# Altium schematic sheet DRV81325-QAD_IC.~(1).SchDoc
size 431 x 279 mm; Date: Not shown in title block; ApprovedBy: Not shown in title block; CheckedBy: Not shown in title block; Author: Not shown in title block; CompanyName: Not shown in title block; Engineer: Not shown in title block; Organization: Not shown in title block; Address1: Not shown in title block; Address2: Not shown in title block; Address3: Not shown in title block; Address4: Not shown in title block; DocumentNumber: 1; Revision: Use project parameter SCH_Rev; SheetNumber: 3; SheetTotal: 5; PageSetup: Record=PageOptions¦CenterHorizontal=True¦CenterVertical=True¦PrintScale=1.00¦XCorrection=1.00¦YCorrection=1.00¦PrintKind=0¦BorderSize=5000000¦LeftOffset=0¦BottomOffset=0¦Orientation=2¦PaperLength=1000¦PaperWidth=1000¦Scale=100¦PaperSource=15¦PrintQuality=600¦MediaType=1¦DitherType=10¦PaperKind=Letter¦PrintScaleMode=1
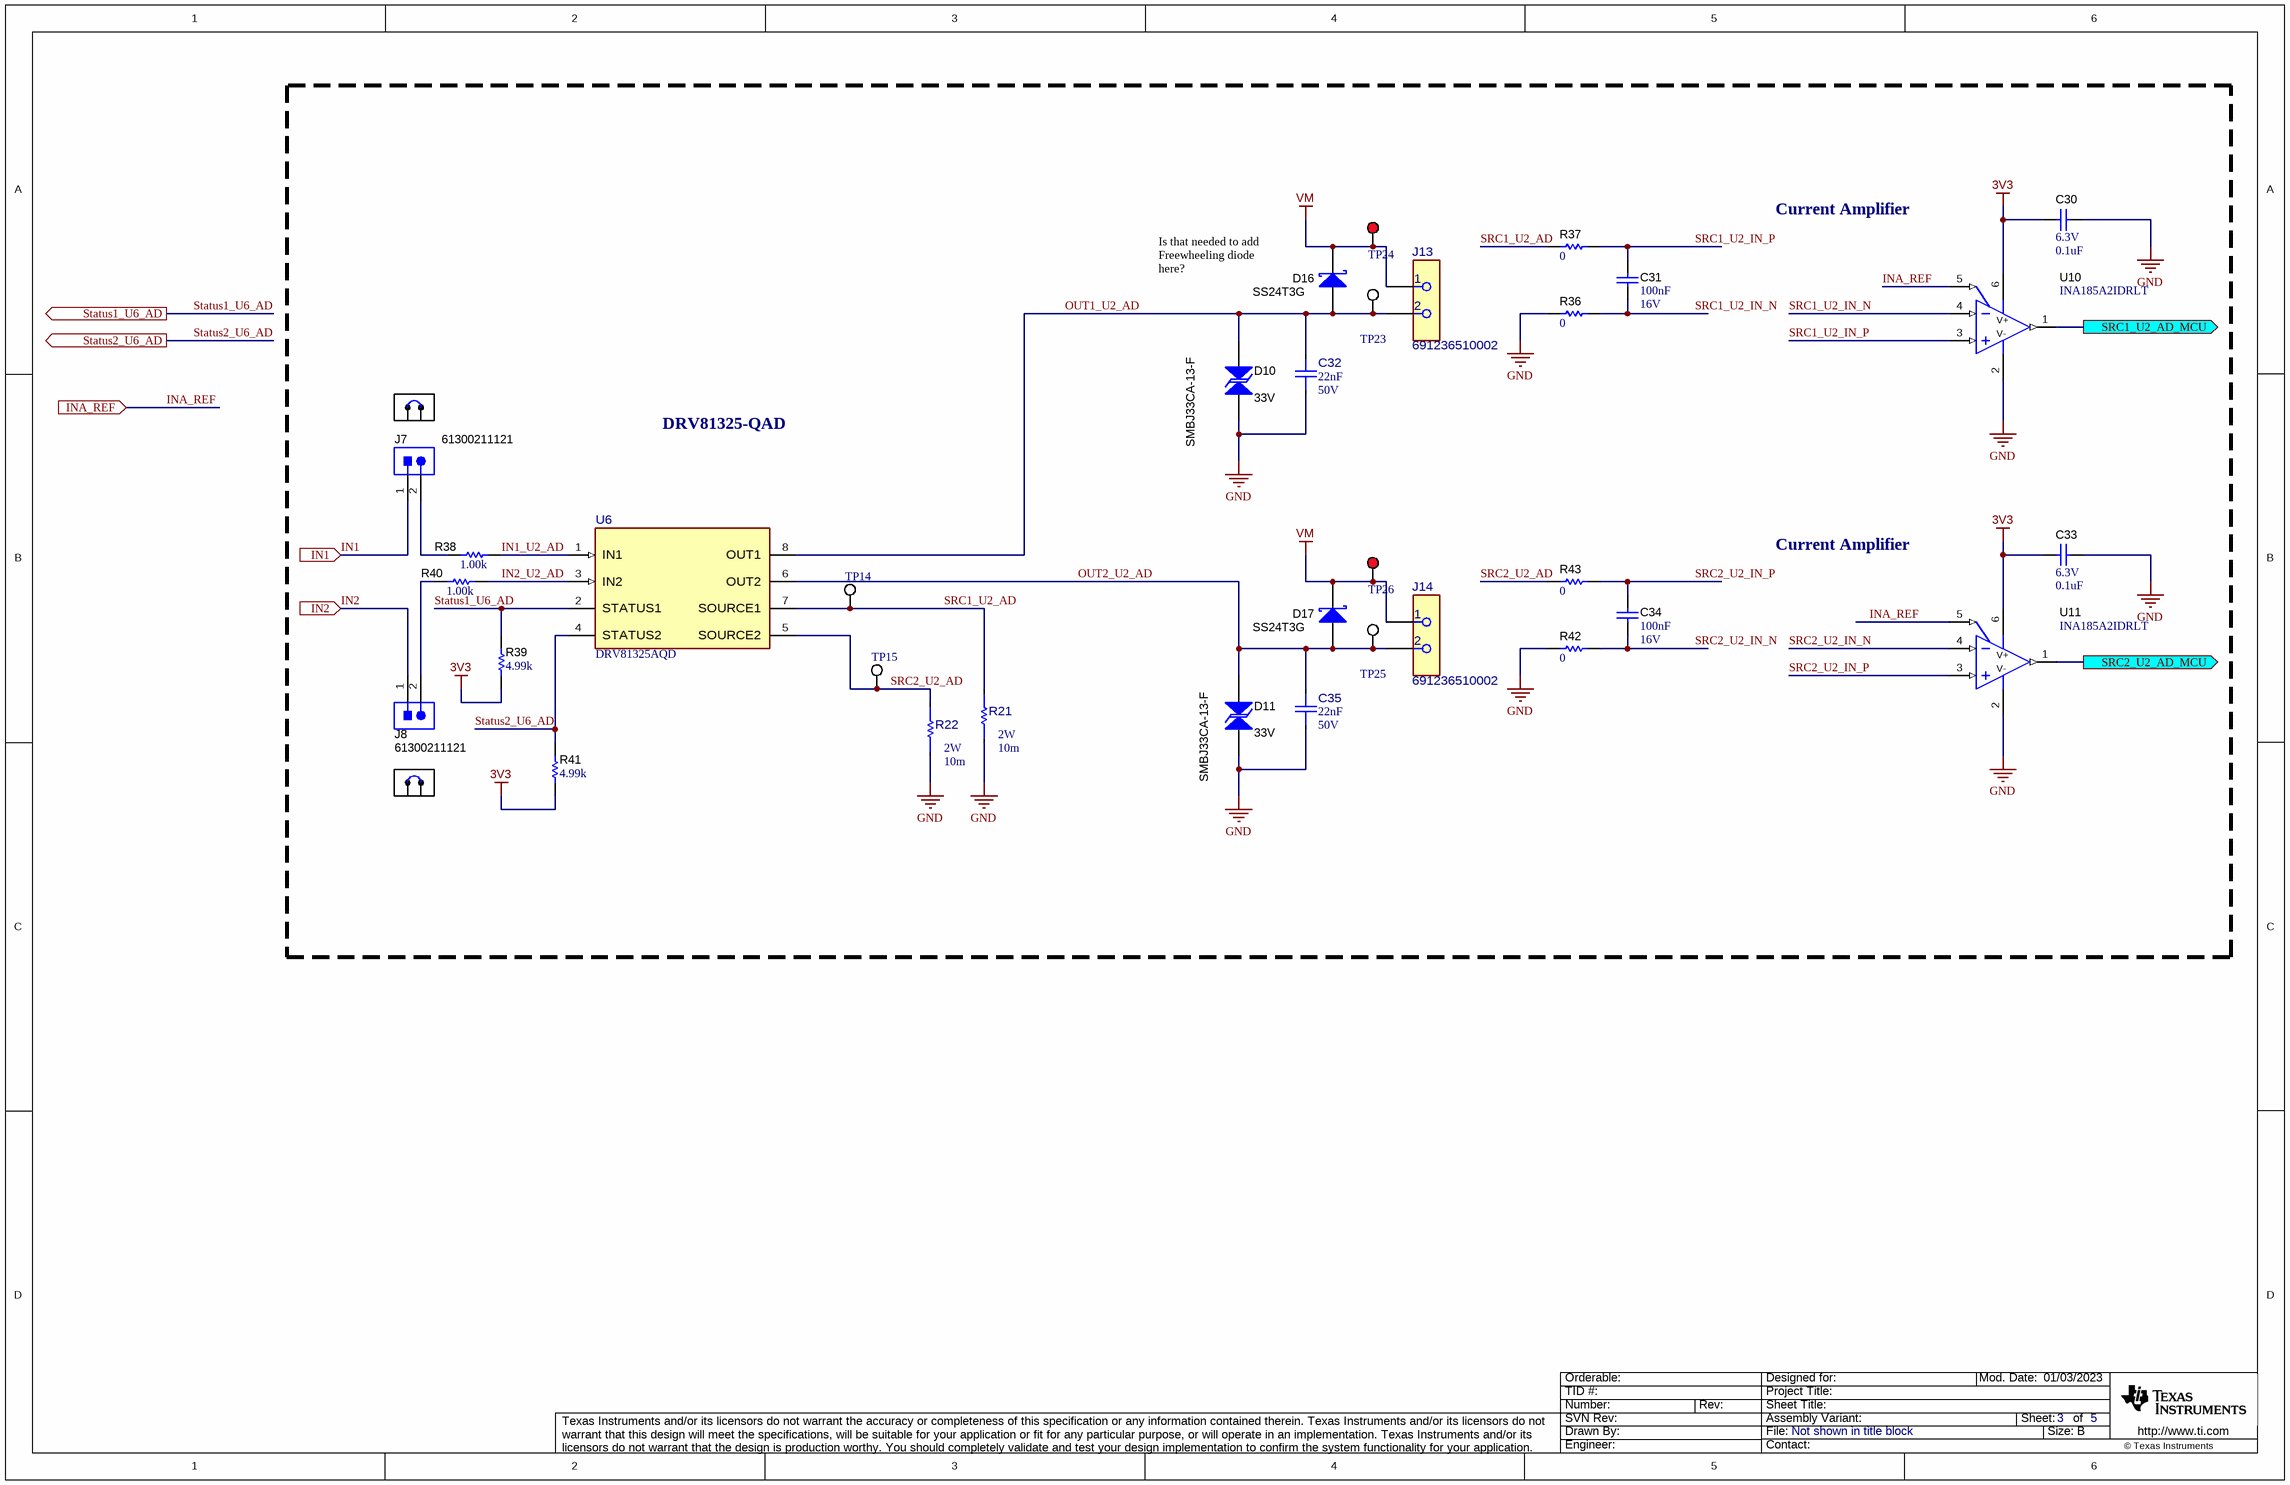
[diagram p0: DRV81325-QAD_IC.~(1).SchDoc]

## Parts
C30  VDC_V: 6.3V  ValueDisplayed: 0.1uF  [0402]  (hidden comment: 885012105001)
C31  Cap_F: 100nF  VDC_V: 16V  [0603]  (hidden comment: 885012206046)
C32  Cap_F: 22nF  VDC_V: 50V  [FP-885012206091_0603-MFG]  (hidden comment: 885012206091)
C33  VDC_V: 6.3V  ValueDisplayed: 0.1uF  [0402]  (hidden comment: 885012105001)
C34  Cap_F: 100nF  VDC_V: 16V  [0603]  (hidden comment: 885012206046)
C35  Cap_F: 22nF  VDC_V: 50V  [FP-885012206091_0603-MFG]  (hidden comment: 885012206091)
D10  SMBJ33CA-13-F  value 33V  [SMB-Bi]
D11  SMBJ33CA-13-F  value 33V  [SMB-Bi]
D16  SS24T3G  [SMB]
D17  SS24T3G  [SMB]
J7  61300211121  [WURTH_61300211121]
J8  61300211121  [WURTH_61300211121]
J13  691236510002  [FP-691236510002_HHR2-MFG]
J14  691236510002  [FP-691236510002_HHR2-MFG]
R21  Res_ohm: 10m  Power_W: 2W  [FP-PCS2512DR0100ET_2512-MFG]  (hidden comment: PCS2512DR0100ET)
R22  Res_ohm: 10m  Power_W: 2W  [FP-PCS2512DR0100ET_2512-MFG]  (hidden comment: PCS2512DR0100ET)
R36  ValueDisplayed: 0  [0603]  (hidden comment: ERJ-3GEY0R00V)
R37  ValueDisplayed: 0  [0603]  (hidden comment: ERJ-3GEY0R00V)
R38  ValueDisplayed: 1.00k  [0603]  (hidden comment: RC0603FR-071KL)
R39  ValueDisplayed: 4.99k  [0603]  (hidden comment: RC0603FR-074K99L)
R40  ValueDisplayed: 1.00k  [0603]  (hidden comment: RC0603FR-071KL)
R41  ValueDisplayed: 4.99k  [0603]  (hidden comment: RC0603FR-074K99L)
R42  ValueDisplayed: 0  [0603]  (hidden comment: ERJ-3GEY0R00V)
R43  ValueDisplayed: 0  [0603]  (hidden comment: ERJ-3GEY0R00V)
SH-J7  60900213421  [Wurth_60900213421]  (value not drawn)
SH-J8  60900213421  [Wurth_60900213421]  (value not drawn)
TP14  5002  [Keystone5002]  (value not drawn)
TP15  5002  [Keystone5002]  (value not drawn)
TP23  5012  [Keystone5012]  (value not drawn)
TP24  5010  [Keystone5010]  (value not drawn)
TP25  5012  [Keystone5012]  (value not drawn)
TP26  5010  [Keystone5010]  (value not drawn)
U6  DRV81325AQD  [D0008A-MFG]
U10  INA185A2IDRLT  [DRL0006A]
U11  INA185A2IDRLT  [DRL0006A]

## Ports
IN1 (in), IN2 (in), INA_REF (in), SRC1_U2_AD_MCU (out), SRC2_U2_AD_MCU (out), Status1_U6_AD (out), Status2_U6_AD (out)

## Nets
3V3: C30.2 C33.2 R39.1 R41.1 U10.6(V+) U11.6(V+)
GND: C30.1 C32.1 C33.1 C35.1 D10.1 D11.1 R21.1 R22.1 R36.1 R42.1 U10.2(V-) U11.2(V-)
VM: D16.1(K) D17.1(K) J13.1 J14.1 TP24.1 TP26.1
IN1: J7.1 ; port IN1
IN1_U2_AD: R38.2 U6.1(IN1)
IN2: J8.1 ; port IN2
IN2_U2_AD: R40.2 U6.3(IN2)
INA_REF: U10.5(REF) U11.5(REF) ; port INA_REF
OUT1_U2_AD: C32.2 D10.2 D16.2(A) J13.2 TP23.1 U6.8(OUT1)
OUT2_U2_AD: C35.2 D11.2 D17.2(A) J14.2 TP25.1 U6.6(OUT2)
SRC1_U2_AD: R21.2 R37.1 TP14.1 U6.7(SOURCE1)
SRC1_U2_AD_MCU: U10.1(OUT) ; port SRC1_U2_AD_MCU
SRC1_U2_IN_N: C31.2 R36.2 U10.4(IN-)
SRC1_U2_IN_P: C31.1 R37.2 U10.3(IN+)
SRC2_U2_AD: R22.2 R43.1 TP15.1 U6.5(SOURCE2)
SRC2_U2_AD_MCU: U11.1(OUT) ; port SRC2_U2_AD_MCU
SRC2_U2_IN_N: C34.2 R42.2 U11.4(IN-)
SRC2_U2_IN_P: C34.1 R43.2 U11.3(IN+)
Status1_U6_AD: R39.2 U6.2(STATUS1) ; port Status1_U6_AD
Status2_U6_AD: R41.2 U6.4(STATUS2) ; port Status2_U6_AD
NetJ7_2: J7.2 R38.1
NetJ8_2: J8.2 R40.1

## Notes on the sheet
- Current Amplifier
- Is that needed to add Freewheeling diode here?
- DRV81325-QAD

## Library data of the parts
C30 C33 = CMP-0006219-2: CAP, CERM, 0.1 uF, 6.3 V, +/- 20%, X5R, 0402; Manufacturer: Wurth Elektronik; TaMin_C: -55°C; Polarized: N; SizeAreaWB_mm2: 3; Value1: Unknown; U/M: EA; Value: 0.1uF; TaMax_C: 85°C; SizeZ_mm: 0.6; SizeX_mm: 1; SizeY_mm: 0.5; Cap_F: 100nF; AEC Category: Q200
C31 C34 = CMP-0006829-4: CAP, CERM, 0.1 uF, 16 V, +/- 10%, X7R, 0603; Manufacturer: Wurth Elektronik; TaMin_C: -55°C; Polarized: N; SizeAreaWB_mm2: 4.68; Value1: Unknown; U/M: EA; Value: 0.1uF; TaMax_C: 125°C; SizeZ_mm: 1; SizeX_mm: 1.6; SizeY_mm: 0.8; SizeArea_mm2: 1.28; AEC Category: Q200
C32 C35 = CMP-0120895-1: 0.022 µF ±10% 50V Ceramic Capacitor X7R 0603 (1608 Metric); Manufacturer: Wurth Electronics; AEC Qualified: No; SizeZ_mm: 0.87mm; TempCo: 15%; Value: 22nF
D10 D11 = CMP-0005564-3: Diode, TVS, Bi, 33 V, SMB; Manufacturer: Diodes Inc.; SizeX_mm: 5.6; Ppk: 600W; SizeAreaWB_mm2: 44.156; SizeZ_mm: 2.6; SizeArea_mm2: 21.336; SizeY_mm: 3.81; AEC Category: Q101
D16 D17 = CMP-0028778-2: Diode, Schottky, 40 V, 2 A, AEC-Q101, SMB; Manufacturer: ON Semiconductor; AEC Qualified: Y; Value: 40V; TJmax_C: 150°C; Value1: 2A; Green_Lifecycle: Active; Value2: 0.5V; SizeX_mm: 5.6; SizeAreaWB_mm2: 44.156; SizeY_mm: 3.81; SizeArea_mm2: 21.336; Green_REACh: Passed; SizeZ_mm: 2.6; AEC Category: Q101; Vf_V: 500mV
J7 J8 = CMP-0054794-2: Header, 2.54 mm, 2x1, Gold, TH; Manufacturer: Wurth Elektronik; Shrouded: N; Gender: Male; Green_REACh: Passed; Pitch_mm: 2.54; Green_Lifecycle: Active; Row_Count: 1; Cert_UL: Y
J13 J14 = CMP-0121282-1: 2 Position Wire to Board Terminal Block Horizontal with Board 0.200" (5.08mm) Through Hole; Manufacturer: Wurth Electronics; Current_A: 20A; Row_Count: 1; Voltage_V: 300V; AEC Qualified: No; Conn Gender: Female; Is Female: yes; Max Wire Gauge: 12; Min Wire Gauge: 30; SizeZ_mm: 18.1mm
R21 R22 = CMP-0088493-1: 10 mOhms ±0.5% 2W Chip Resistor 2512 (6432 Metric) Automotive AEC-Q200, Current Sense, Moisture Resistant Metal Film; Manufacturer: Ohmite; SizeZ_mm: 0.664mm; AEC Grade: Grade 0; TempCo: 50ppm/°C; AEC Qualified: Yes; Tolerance_%: 0%
R36 R37 R42 R43 = CMP-0025874-4: RES, 0, 5%, 0.1 W, AEC-Q200 Grade 0, 0603; Manufacturer: Panasonic; Power_W: 100mW; TempCo: 600 ppm/C; Value_Code: 0000; Value: 0; EIA_Code: E24; SizeX_mm: 1.6; SizeY_mm: 0.8; SizeZ_mm: 1; Value2: 0.1W; SizeArea_mm2: 1.28; AEC Qualified: Y; VDC_V: 50V; AEC Category: Q200; SizeAreaWB_mm2: 4.68
R38 R40 = CMP-0022895-5: RES, 1.00 k, 1%, 0.1 W, 0603; Manufacturer: Yageo; Power_W: 100mW; TempCo: 100 ppm/C; Value_Code: 1k00; Value: 1.00k; EIA_Code: E96; Res_ohm: 1k; SizeX_mm: 1.6; SizeY_mm: 0.8; SizeZ_mm: 1; Value2: 0.1W; SizeArea_mm2: 1.28; AEC Qualified: N; VDC_V: 75V; AEC Category: Q200; SizeAreaWB_mm2: 4.68
R39 R41 = CMP-0023155-5: RES, 4.99 k, 1%, 0.1 W, 0603; Manufacturer: Yageo; Power_W: 100mW; TempCo: 100 ppm/C; Value_Code: 4k99; Value: 4.99k; EIA_Code: E96; SizeX_mm: 1.6; SizeY_mm: 0.8; SizeZ_mm: 1; Value2: 0.1W; SizeArea_mm2: 1.28; AEC Qualified: N; VDC_V: 75V; AEC Category: Q200; SizeAreaWB_mm2: 4.68
SH-J7 SH-J8 = CMP-0003761-2: Shunt, 2.54mm, Gold, Black; Manufacturer: Wurth Elektronik
TP14 TP15 = CMP-0055139-2: Test Point, Miniature, White, TH; Manufacturer: Keystone Electronics; ContactFinish: Silver; Green_REACh: Passed; CT: TRUE; Green_Lifecycle: Active; CNHeader: FALSE
TP23 TP25 = CMP-0055149-2: Test Point, Multipurpose, White, TH; Manufacturer: Keystone Electronics; ContactFinish: Silver; CT: TRUE; CNHeader: FALSE; Green_Lifecycle: Active; Green_REACh: Passed
TP24 TP26 = CMP-0055147-2: Test Point, Multipurpose, Red, TH; Manufacturer: Keystone Electronics; CT: TRUE; ContactFinish: Silver; Green_Lifecycle: Active; CNHeader: FALSE; Green_REACh: Passed
U6 = CMP-0127803-1: Manufacturer: Texas Instruments; SizeZ_mm: 1.75mm; Standoff Height: 0.11mm
U10 U11 = CMP-0085241-1: Bidirectional, Precision Low- and High-Side Voltage Output, Current-Sense Amplifier, DRL0006A (SOT-5X3-6); Alternate Manufacturer: Texas Instruments; Alternate PartNumber: INA185A2IDRLR; SizeZ_mm: 0.6; CompType: IC; SizeY_mm: 1.6; SizeAreaWB_mm2: 6.76; AEC Qualified: N; SizeArea_mm2: 2.56; AEC Category: Q200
